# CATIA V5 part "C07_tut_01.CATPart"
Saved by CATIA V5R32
Part number: Part1
Bounding box of the stored display mesh (mm): x -150 to 150, y -150 to 150, z -127.513 to 0
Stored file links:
  D:\PROJECTS\Project 2022\CATIA V5 6R 2022\Resources\Tutorial Files\c07_catia_v5_6r2022_tut\C07_tut_01.CATPart
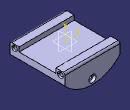
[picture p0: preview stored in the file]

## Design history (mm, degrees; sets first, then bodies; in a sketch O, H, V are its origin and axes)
Body1 (main body)
  Sketch1 on zx-plane, origin (0, 0, 0), H (-1, 0, 0), V (0, 0, 1)
    point P1 (-150, 0)
    line L1 (-150, 0) -> (150, 0)
    point P2 (150, 0)
    line L2 (150, 0) -> (150, -60)
    point P3 (150, -60)
    point P4 (-150, -60)
    point P5 (-150, 0)
    line L3 (-150, 0) -> (-150, -60)
    arc A1 centre (0, 72.2876) radius 200 from (150, -60) to (-150, -60) cw
    point P7 (0, -127.7124)
    length L1 = 300
    length L2 = 60
    radius A1 = 200
    horizontal: L1 H
    vertical: L2 V
    symmetry: P1 P2 V, P3 P4 V, P2 P5 V, L2 L3 V
    coincidence: L1 H, A1 P7, P7 V, P1 P5
  Pad1: profile Sketch1, direction (0, 1, 0), length 150, mirrored extent
  Sketch2 on yz-plane, origin (0, 0, 0), H (0, 1, 0), V (0, 0, 1)
    line L1 (100, 0) -> (-100, 0)
    reference projected line E1 (-150, 0) -> (150, 0) from edge [face of Pad1 from Sketch1.L3 | face of Pad1 from Sketch1.L1]
    line L2 (-100, 0) -> (-100, -25)
    line L3 (-100, -25) -> (100, -25)
    line L4 (100, -25) -> (100, 0)
    length L1 = 200
    length L4 = 25
    distance V L4 = 100
    horizontal: L1 H, L3 H
    coincidence: L1 E1
    vertical: L2 V, L4 V
  Pocket1: profile Sketch2, direction (-1, 0, 0), length 150, mirrored extent
  Fillet1: radius 10, on edge [start face of Pad1 | face of Pad1 from Sketch1.L1]; edge [face of Pad1 from Sketch1.L1 | end face of Pad1]
  Sketch3 on yz-plane, origin (0, 0, 0), H (0, 1, 0), V (0, 0, 1)
    point P1 (-125, -20)
    point P2 (125, -20)
    reference projected line E1 (150, 0) -> (150, -60) from edge [face of Pad1 from Sketch1.L3 | end face of Pad1]
    reference projected line E2 (-150, 0) -> (150, 0) from edge [face of Pad1 from Sketch1.L3 | face of Pad1 from Sketch1.L1]
    distance P2 E1 = 25
    distance P2 E2 = 20
    symmetry: P1 P2 V
  Sketch4 on face of Pad1 from Sketch1.L3, origin (150, 125, -20), H (0, 1, 0), V (0, 0, 1)
    point P1 (0, 0)
    reference projected point E1 (0, 0) from Sketch3.P2
    coincidence: E1 P1
  Hole1: placed by Sketch4, at (150, 125, -20) direction (-1, 0, 0), diameter 20, through (limit type 3), countersink depth 5, countersink angle 90
  Sketch5 on face of Pad1 from Sketch1.L3, origin (150, -125, -20), H (0, 1, 0), V (0, 0, 1)
    point P1 (0, 0)
    reference projected point E1 (0, 0) from Sketch3.P1
    coincidence: E1 P1
  Hole2: placed by Sketch5, at (150, -125, -20) direction (-1, 0, 0), diameter 20, through (limit type 3), countersink depth 5, countersink angle 90
  Sketch6 on zx-plane, origin (0, 0, 0), H (-1, 0, 0), V (0, 0, 1)
    point P1 (0, -100)
    distance P1 H = 100
    coincidence: P1 V
  Sketch7 on end face of Pad1, origin (0, 150, -100), H (1, 0, 0), V (0, 0, -1)
    point P1 (0, 0)
    reference projected point E1 (0, 0) from Sketch6.P1
    coincidence: E1 P1
  Hole3: placed by Sketch7, at (0, 150, -100) direction (0, -1, 0), diameter 20, through (limit type 3), counterbore diameter 40, counterbore depth 15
